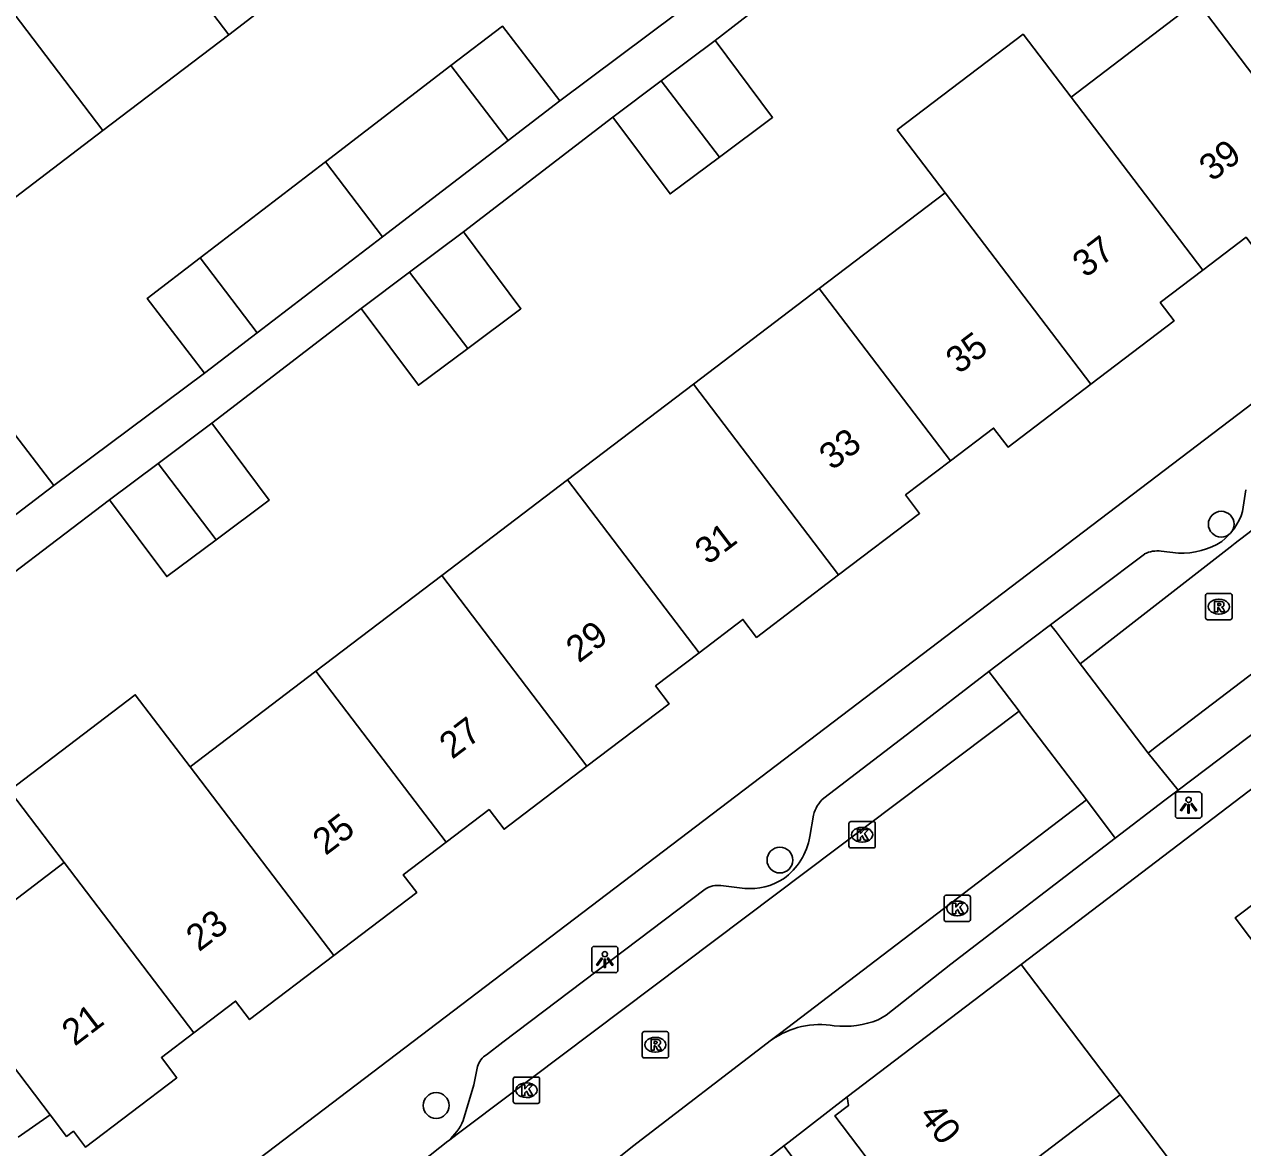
# Model space of a CAD drawing. Extents: x 160037 to 160839, y 385326 to 386441.
# Drawn here: x 160402.85 to 160449.09, y 385706.97 to 385749.61 of the extents above; entities that cross this region are included whole.
import ezdxf

# ---------------------------------------------------------------- set-up
doc = ezdxf.new("R2010")
doc.units = 0
for name, color, linetype in [('IMGEO_Boom', 7, 'Continuous'), ('IMGEO_Erf', 7, 'Continuous'), ('IMGEO_Kolk', 7, 'Continuous'), ('IMGEO_Lichtpunt', 7, 'Continuous'), ('IMGEO_Muur', 7, 'Continuous'), ('IMGEO_Pand', 7, 'Continuous'), ('IMGEO_Pand_nummerreeks', 7, 'Continuous'), ('IMGEO_Rijbaan_lokaal_open', 7, 'Continuous'), ('IMGEO_Rioolput', 7, 'Continuous'), ('IMGEO_Voetpad_open', 7, 'Continuous')]:
    doc.layers.add(name, color=color, linetype=linetype)

msp = doc.modelspace()

# ---------------------------------------------------------------- linework, layer by layer
at = {"layer": 'IMGEO_Boom'}
for centre in [(160448.279, 385730.633), (160431.529, 385717.884), (160418.482, 385708.569)]:
    msp.add_circle(centre, 0.489, dxfattribs=at)
at = {"layer": 'IMGEO_Erf'}
msp.add_lwpolyline([(160403.833, 385708.209), (160402.624, 385707.372)], dxfattribs=at)
at = {"layer": 'IMGEO_Kolk'}
for p, q in [((160434.148, 385718.419), (160434.148, 385719.271)), ((160434.223, 385719.345), (160435.075, 385719.345)), ((160435.149, 385719.271), (160435.149, 385718.419)), ((160434.636, 385719.125), (160434.661, 385719.125)), ((160435.075, 385718.345), (160434.223, 385718.345)), ((160434.659, 385718.565), (160434.634, 385718.565)), ((160437.761, 385715.624), (160437.761, 385716.476)), ((160437.836, 385716.55), (160438.688, 385716.55)), ((160438.762, 385716.476), (160438.762, 385715.624)), ((160438.249, 385716.33), (160438.274, 385716.33)), ((160438.688, 385715.55), (160437.836, 385715.55)), ((160438.272, 385715.77), (160438.247, 385715.77)), ((160421.409, 385708.722), (160421.409, 385709.574)), ((160421.484, 385709.648), (160422.336, 385709.648)), ((160422.41, 385709.574), (160422.41, 385708.722)), ((160421.897, 385709.428), (160421.922, 385709.428)), ((160422.336, 385708.648), (160421.484, 385708.648)), ((160421.92, 385708.868), (160421.895, 385708.868))]:
    msp.add_line(p, q, dxfattribs=at)
for points in [[(160434.148, 385718.419), (160434.148, 385719.271)], [(160434.223, 385719.345), (160435.075, 385719.345)], [(160435.149, 385719.271), (160435.149, 385718.419)], [(160434.469, 385719.045), (160434.592, 385719.045), (160434.592, 385718.894), (160434.722, 385719.045), (160434.886, 385719.045), (160434.74, 385718.894), (160434.893, 385718.645), (160434.741, 385718.645), (160434.656, 385718.809), (160434.592, 385718.742), (160434.592, 385718.645), (160434.469, 385718.645), (160434.469, 385719.045)], [(160435.075, 385718.345), (160434.223, 385718.345)], [(160437.761, 385715.624), (160437.761, 385716.476)], [(160437.836, 385716.55), (160438.688, 385716.55)], [(160438.762, 385716.476), (160438.762, 385715.624)], [(160438.082, 385716.25), (160438.205, 385716.25), (160438.205, 385716.099), (160438.335, 385716.25), (160438.499, 385716.25), (160438.353, 385716.099), (160438.506, 385715.85), (160438.354, 385715.85), (160438.269, 385716.014), (160438.205, 385715.947), (160438.205, 385715.85), (160438.082, 385715.85), (160438.082, 385716.25)], [(160438.688, 385715.55), (160437.836, 385715.55)], [(160421.409, 385708.722), (160421.409, 385709.574)], [(160421.484, 385709.648), (160422.336, 385709.648)], [(160422.41, 385709.574), (160422.41, 385708.722)], [(160421.73, 385709.348), (160421.853, 385709.348), (160421.853, 385709.197), (160421.983, 385709.348), (160422.147, 385709.348), (160422.001, 385709.197), (160422.154, 385708.948), (160422.002, 385708.948), (160421.917, 385709.112), (160421.853, 385709.045), (160421.853, 385708.948), (160421.73, 385708.948), (160421.73, 385709.348)], [(160422.336, 385708.648), (160421.484, 385708.648)]]:
    msp.add_lwpolyline(points, dxfattribs=at)
for centre, start, end in [((160434.225, 385719.269), 91.552, 178.448), ((160434.225, 385719.269), 91.552, 178.448), ((160435.073, 385719.269), 1.552, 88.448), ((160435.073, 385719.269), 1.552, 88.448), ((160434.225, 385718.421), 181.552, 268.448), ((160434.225, 385718.421), 181.552, 268.448), ((160435.073, 385718.421), 271.552, 358.448), ((160435.073, 385718.421), 271.552, 358.448), ((160437.838, 385716.474), 91.552, 178.448), ((160437.838, 385716.474), 91.552, 178.448), ((160438.686, 385716.474), 1.552, 88.448), ((160438.686, 385716.474), 1.552, 88.448), ((160437.838, 385715.626), 181.552, 268.448), ((160437.838, 385715.626), 181.552, 268.448), ((160438.686, 385715.626), 271.552, 358.448), ((160438.686, 385715.626), 271.552, 358.448), ((160421.486, 385709.572), 91.552, 178.448), ((160421.486, 385709.572), 91.552, 178.448), ((160422.334, 385709.572), 1.552, 88.448), ((160422.334, 385709.572), 1.552, 88.448), ((160421.486, 385708.724), 181.552, 268.448), ((160421.486, 385708.724), 181.552, 268.448), ((160422.334, 385708.724), 271.552, 358.448), ((160422.334, 385708.724), 271.552, 358.448)]:
    msp.add_arc(centre, 0.0765, start, end, dxfattribs=at)
for centre, major_axis, ratio, start_param, end_param in [((160434.635, 385718.845), (-0.387, 0.002), 0.722429, 4.712389, 7.853982), ((160434.66, 385718.845), (-0.39, 0.002), 0.717154, 1.570796, 4.712389), ((160438.248, 385716.05), (-0.387, 0.002), 0.722429, 4.712389, 7.853982), ((160438.273, 385716.05), (-0.39, 0.002), 0.717154, 1.570796, 4.712389), ((160421.896, 385709.148), (-0.387, 0.002), 0.722429, 4.712389, 7.853982), ((160421.921, 385709.148), (-0.39, 0.002), 0.717154, 1.570796, 4.712389)]:
    msp.add_ellipse(centre, major_axis=major_axis, ratio=ratio, start_param=start_param, end_param=end_param, dxfattribs=at)
at = {"layer": 'IMGEO_Lichtpunt'}
for p, q in [((160446.541, 385720.374), (160446.541, 385719.567)), ((160446.541, 385720.374), (160446.541, 385719.567)), ((160447.443, 385720.469), (160446.635, 385720.469)), ((160447.443, 385720.469), (160446.635, 385720.469)), ((160447.537, 385719.567), (160447.537, 385720.374)), ((160447.537, 385719.567), (160447.537, 385720.374)), ((160446.635, 385719.473), (160447.443, 385719.473)), ((160446.635, 385719.473), (160447.443, 385719.473)), ((160425.288, 385714.607), (160424.48, 385714.607)), ((160425.288, 385714.607), (160424.48, 385714.607)), ((160424.386, 385714.512), (160424.386, 385713.705)), ((160424.386, 385714.512), (160424.386, 385713.705)), ((160425.382, 385713.705), (160425.382, 385714.512)), ((160425.382, 385713.705), (160425.382, 385714.512)), ((160424.48, 385713.611), (160425.288, 385713.611)), ((160424.48, 385713.611), (160425.288, 385713.611))]:
    msp.add_line(p, q, dxfattribs=at)
for points in [[(160446.915, 385720.038), (160446.954, 385720.01), (160446.766, 385719.748), (160446.728, 385719.775), (160446.915, 385720.038)], [(160447.017, 385719.99), (160447.064, 385719.99), (160447.064, 385719.668), (160447.017, 385719.668), (160447.017, 385719.99)], [(160447.127, 385720.01), (160447.165, 385720.037), (160447.352, 385719.775), (160447.313, 385719.747), (160447.127, 385720.01)], [(160424.76, 385714.176), (160424.799, 385714.148), (160424.611, 385713.886), (160424.573, 385713.913), (160424.76, 385714.176)], [(160424.972, 385714.148), (160425.01, 385714.175), (160425.197, 385713.913), (160425.158, 385713.885), (160424.972, 385714.148)], [(160424.862, 385714.128), (160424.909, 385714.128), (160424.909, 385713.806), (160424.862, 385713.806), (160424.862, 385714.128)]]:
    msp.add_lwpolyline(points, dxfattribs=at)
for centre in [(160447.04, 385720.172), (160424.885, 385714.31)]:
    msp.add_circle(centre, 0.0994, dxfattribs=at)
for centre, start, end in [((160446.635, 385720.374), 90, 180), ((160446.635, 385720.374), 90, 180), ((160447.443, 385720.374), 0, 90), ((160447.443, 385720.374), 0, 90), ((160446.635, 385719.567), 180, 270), ((160446.635, 385719.567), 180, 270), ((160447.443, 385719.567), 270, 0), ((160447.443, 385719.567), 270, 360), ((160424.48, 385714.512), 90, 180), ((160424.48, 385714.512), 90, 180), ((160425.288, 385714.512), 0, 90), ((160425.288, 385714.512), 0, 90), ((160424.48, 385713.705), 180, 270), ((160424.48, 385713.705), 180, 270), ((160425.288, 385713.705), 270, 0), ((160425.288, 385713.705), 270, 360)]:
    msp.add_arc(centre, 0.0946, start, end, dxfattribs=at)
at = {"layer": 'IMGEO_Muur'}
msp.add_lwpolyline([(160449.644, 385720.741), (160449.342, 385720.511), (160440.682, 385713.917)], dxfattribs=at)
at = {"layer": 'IMGEO_Pand'}
for points in [[(160410.611, 385749.212), (160410.011, 385750), (160405.606, 385755.787)], [(160400.314, 385752.834), (160402.472, 385750), (160405.838, 385745.578)], [(160410.611, 385749.212), (160411.646, 385750), (160415.385, 385752.847)], [(160447.353, 385750.475), (160446.728, 385750), (160442.577, 385746.843)], [(160447.353, 385750.475), (160447.714, 385750), (160452.864, 385743.228)], [(160423.172, 385746.702), (160420.997, 385749.539), (160419.044, 385748.041)], [(160405.838, 385745.578), (160410.611, 385749.212)], [(160427.028, 385747.465), (160429.076, 385748.994)], [(160429.232, 385744.567), (160431.254, 385746.077), (160429.076, 385748.994)], [(160442.577, 385746.843), (160440.761, 385749.231), (160435.985, 385745.6), (160437.801, 385743.212)], [(160419.044, 385748.041), (160414.282, 385744.39)], [(160421.21, 385745.197), (160419.044, 385748.041)], [(160425.186, 385746.089), (160427.028, 385747.465)], [(160429.232, 385744.567), (160427.028, 385747.465)], [(160423.172, 385746.702), (160421.21, 385745.197)], [(160447.575, 385740.27), (160442.577, 385746.843)], [(160425.186, 385746.089), (160427.364, 385743.172), (160429.232, 385744.567)], [(160401.064, 385741.943), (160405.838, 385745.578)], [(160416.447, 385741.545), (160421.21, 385745.197)], [(160414.282, 385744.39), (160409.521, 385740.739)], [(160414.282, 385744.39), (160416.447, 385741.545)], [(160437.801, 385743.212), (160433.025, 385739.58)], [(160437.801, 385743.212), (160443.324, 385735.948)], [(160452.864, 385743.228), (160449.736, 385740.849), (160449.223, 385741.523), (160447.575, 385740.27)], [(160411.687, 385737.894), (160416.447, 385741.545)], [(160419.524, 385741.73), (160417.477, 385740.202)], [(160419.681, 385737.304), (160421.702, 385738.813), (160419.524, 385741.73)], [(160409.521, 385740.739), (160407.515, 385739.201), (160409.69, 385736.363)], [(160411.687, 385737.894), (160409.521, 385740.739)], [(160417.477, 385740.202), (160415.634, 385738.825)], [(160419.681, 385737.304), (160417.477, 385740.202)], [(160447.575, 385740.27), (160445.963, 385739.044), (160446.488, 385738.354), (160443.324, 385735.948)], [(160433.025, 385739.58), (160428.25, 385735.948)], [(160433.025, 385739.58), (160438.001, 385733.037)], [(160415.634, 385738.825), (160417.812, 385735.908), (160419.681, 385737.304)], [(160409.69, 385736.363), (160411.687, 385737.894)], [(160428.25, 385735.948), (160423.473, 385732.316)], [(160428.25, 385735.948), (160433.756, 385728.707)], [(160443.324, 385735.948), (160440.188, 385733.563), (160439.64, 385734.284), (160438.001, 385733.037)], [(160403.968, 385732.099), (160401.824, 385734.899), (160399.967, 385733.477)], [(160407.926, 385732.937), (160409.973, 385734.466)], [(160410.129, 385730.039), (160412.151, 385731.549), (160409.973, 385734.466)], [(160407.926, 385732.937), (160406.083, 385731.561)], [(160410.129, 385730.039), (160410.093, 385730.086), (160407.926, 385732.937)], [(160438.001, 385733.037), (160436.3, 385731.744), (160436.831, 385731.045), (160433.756, 385728.707)], [(160423.473, 385732.316), (160418.697, 385728.684)], [(160428.463, 385725.753), (160423.473, 385732.316)], [(160402.103, 385730.671), (160403.968, 385732.099)], [(160406.083, 385731.561), (160408.261, 385728.644), (160410.129, 385730.039)], [(160418.697, 385728.684), (160413.922, 385725.052)], [(160418.697, 385728.684), (160424.201, 385721.445)], [(160433.756, 385728.707), (160430.641, 385726.339), (160430.126, 385727.017), (160428.463, 385725.753)], [(160428.463, 385725.753), (160426.81, 385724.496), (160427.324, 385723.82), (160424.201, 385721.445)], [(160413.922, 385725.052), (160409.146, 385721.42)], [(160413.922, 385725.052), (160418.858, 385718.561)], [(160409.146, 385721.42), (160407.063, 385724.16), (160402.287, 385720.529), (160404.37, 385717.789)], [(160414.593, 385714.256), (160409.146, 385721.42)], [(160424.201, 385721.445), (160421.059, 385719.056), (160420.491, 385719.803), (160418.858, 385718.561)], [(160418.858, 385718.561), (160417.236, 385717.328), (160417.747, 385716.655), (160414.593, 385714.256)], [(160403.833, 385708.209), (160399.414, 385714.02), (160404.37, 385717.789)], [(160404.37, 385717.789), (160409.284, 385711.326)], [(160450.438, 385713.531), (160448.812, 385715.696), (160451.482, 385717.701)], [(160414.593, 385714.256), (160411.402, 385711.83), (160410.869, 385712.532), (160409.284, 385711.326)], [(160440.682, 385713.917), (160434.085, 385708.897)], [(160440.682, 385713.917), (160443.71, 385709.938), (160444.446, 385708.971)], [(160409.284, 385711.326), (160408.053, 385710.39), (160408.64, 385709.619), (160405.176, 385706.985), (160404.715, 385707.591), (160404.454, 385707.393), (160403.833, 385708.209)], [(160437.999, 385704.064), (160436.754, 385705.701), (160435.955, 385705.093), (160433.61, 385708.175), (160434.127, 385708.568), (160434.085, 385708.897)], [(160444.446, 385708.971), (160437.999, 385704.064)], [(160444.446, 385708.971), (160448.079, 385704.196)]]:
    msp.add_lwpolyline(points, dxfattribs=at)
at = {"layer": 'IMGEO_Rijbaan_lokaal_open'}
for points in [[(160442.926, 385725.336), (160448.737, 385729.856), (160448.762, 385729.875), (160460.742, 385739.019), (160461.382, 385739.566)], [(160445.5, 385721.947), (160445.769, 385722.152), (160461, 385733.756), (160461.267, 385733.959)], [(160441.802, 385726.815), (160440.461, 385725.805), (160439.461, 385725.037)], [(160441.802, 385726.815), (160442.008, 385726.544), (160442.926, 385725.336)], [(160445.5, 385721.947), (160443.018, 385725.214), (160442.926, 385725.336)], [(160439.461, 385725.037), (160439.669, 385724.763), (160440.604, 385723.533)], [(160418.95, 385707.231), (160419.336, 385707.522), (160419.79, 385707.863), (160440.604, 385723.533)], [(160440.604, 385723.533), (160440.679, 385723.434), (160443.162, 385720.166)], [(160446.64, 385720.537), (160445.5, 385721.947)], [(160443.162, 385720.166), (160431.562, 385711.329), (160431.215, 385711.065)], [(160444.25, 385718.71), (160443.162, 385720.166)], [(160444.25, 385718.71), (160446.14, 385720.159), (160446.64, 385720.537)], [(160423.388, 385704.97), (160425.94, 385707.013), (160431.215, 385711.065)], [(160417.011, 385705.558), (160417.949, 385706.438), (160418.929, 385707.215), (160418.95, 385707.231)]]:
    msp.add_lwpolyline(points, dxfattribs=at)
at = {"layer": 'IMGEO_Rioolput'}
for p, q in [((160447.687, 385727.078), (160447.687, 385727.93)), ((160447.762, 385728.004), (160448.614, 385728.004)), ((160448.175, 385727.784), (160448.2, 385727.784)), ((160448.688, 385727.93), (160448.688, 385727.078)), ((160448.198, 385727.224), (160448.173, 385727.224)), ((160448.614, 385727.004), (160447.762, 385727.004)), ((160426.376, 385711.374), (160427.228, 385711.374)), ((160426.301, 385710.448), (160426.301, 385711.3)), ((160426.789, 385711.154), (160426.814, 385711.154)), ((160427.302, 385711.3), (160427.302, 385710.448)), ((160426.812, 385710.594), (160426.787, 385710.594)), ((160427.228, 385710.374), (160426.376, 385710.374))]:
    msp.add_line(p, q, dxfattribs=at)
for points in [[(160447.687, 385727.078), (160447.687, 385727.93)], [(160447.762, 385728.004), (160448.614, 385728.004)], [(160448.276, 385727.702), (160448.024, 385727.704), (160448.024, 385727.304)], [(160448.202, 385727.623), (160448.148, 385727.623), (160448.148, 385727.542)], [(160448.688, 385727.93), (160448.688, 385727.078)], [(160448.024, 385727.304), (160448.148, 385727.304), (160448.148, 385727.466), (160448.159, 385727.466)], [(160448.148, 385727.542), (160448.2, 385727.542)], [(160448.206, 385727.437), (160448.277, 385727.304), (160448.417, 385727.304), (160448.352, 385727.43)], [(160448.614, 385727.004), (160447.762, 385727.004)], [(160426.376, 385711.374), (160427.228, 385711.374)], [(160426.301, 385710.448), (160426.301, 385711.3)], [(160426.89, 385711.072), (160426.638, 385711.074), (160426.638, 385710.674)], [(160426.816, 385710.993), (160426.762, 385710.993), (160426.762, 385710.912)], [(160426.762, 385710.912), (160426.814, 385710.912)], [(160427.302, 385711.3), (160427.302, 385710.448)], [(160426.638, 385710.674), (160426.762, 385710.674), (160426.762, 385710.836), (160426.773, 385710.836)], [(160426.82, 385710.807), (160426.891, 385710.674), (160427.031, 385710.674), (160426.966, 385710.8)], [(160427.228, 385710.374), (160426.376, 385710.374)]]:
    msp.add_lwpolyline(points, dxfattribs=at)
for centre, radius, start, end in [((160447.764, 385727.928), 0.0765, 91.552, 178.448), ((160447.764, 385727.928), 0.0765, 91.552, 178.448), ((160448.208, 385727.527), 0.0964, 77.0061, 93.1865), ((160448.222, 385727.584), 0.0378, 276.6634, 79.6772), ((160448.275, 385727.592), 0.109, 350.3612, 89.416), ((160448.273, 385727.592), 0.112, 277.5842, 350.9817), ((160448.612, 385727.928), 0.0765, 1.552, 88.448), ((160448.612, 385727.928), 0.0765, 1.552, 88.448), ((160448.158, 385727.413), 0.0533, 26.0293, 88.6989), ((160448.184, 385727.731), 0.19, 274.7715, 282.9687), ((160448.257, 385727.377), 0.108, 29.5134, 73.7905), ((160447.764, 385727.08), 0.0765, 181.552, 268.448), ((160447.764, 385727.08), 0.0765, 181.552, 268.448), ((160448.612, 385727.08), 0.0765, 271.552, 358.448), ((160448.612, 385727.08), 0.0765, 271.552, 358.448), ((160426.378, 385711.298), 0.0765, 91.552, 178.448), ((160426.378, 385711.298), 0.0765, 91.552, 178.448), ((160427.226, 385711.298), 0.0765, 1.552, 88.448), ((160427.226, 385711.298), 0.0765, 1.552, 88.448), ((160426.798, 385711.101), 0.19, 274.7715, 282.9687), ((160426.822, 385710.897), 0.0964, 77.0061, 93.1865), ((160426.836, 385710.954), 0.0378, 276.6634, 79.6772), ((160426.889, 385710.962), 0.109, 350.3612, 89.416), ((160426.887, 385710.962), 0.112, 277.5842, 350.9817), ((160426.378, 385710.45), 0.0765, 181.552, 268.448), ((160426.378, 385710.45), 0.0765, 181.552, 268.448), ((160426.772, 385710.783), 0.0533, 26.0293, 88.6989), ((160426.871, 385710.747), 0.108, 29.5134, 73.7905), ((160427.226, 385710.45), 0.0765, 271.552, 358.448), ((160427.226, 385710.45), 0.0765, 271.552, 358.448)]:
    msp.add_arc(centre, radius, start, end, dxfattribs=at)
for centre, major_axis, ratio, start_param, end_param in [((160448.174, 385727.504), (-0.387, 0.002), 0.722429, 4.712389, 7.853982), ((160448.199, 385727.504), (-0.39, 0.002), 0.717154, 1.570796, 4.712389), ((160426.788, 385710.874), (-0.387, 0.002), 0.722429, 4.712389, 7.853982), ((160426.813, 385710.874), (-0.39, 0.002), 0.717154, 1.570796, 4.712389)]:
    msp.add_ellipse(centre, major_axis=major_axis, ratio=ratio, start_param=start_param, end_param=end_param, dxfattribs=at)
at = {"layer": 'IMGEO_Voetpad_open'}
for points in [[(160429.076, 385748.994), (160431.915, 385751.209)], [(160428.786, 385750.901), (160423.172, 385746.702)], [(160419.524, 385741.73), (160425.186, 385746.089)], [(160440.882, 385659.407), (160407.478, 385703.294), (160463, 385745.517)], [(160409.973, 385734.466), (160415.634, 385738.825)], [(160409.69, 385736.363), (160403.968, 385732.099)], [(160449.213, 385731.941), (160449.091, 385731.113)], [(160400.184, 385727.073), (160406.083, 385731.561)], [(160446.64, 385720.537), (160454.889, 385726.781), (160459.579, 385730.435)], [(160445.367, 385729.502), (160441.802, 385726.815)], [(160446.656, 385729.533), (160445.999, 385729.607)], [(160433.195, 385720.23), (160436.537, 385722.794), (160439.461, 385725.037)], [(160449.342, 385720.511), (160440.682, 385713.917)], [(160432.66, 385718.775), (160432.802, 385719.594)], [(160435.257, 385711.822), (160435.568, 385712.002), (160438.016, 385713.932), (160444.25, 385718.71)], [(160429.287, 385716.918), (160430.195, 385716.811)], [(160420.395, 385710.497), (160421.016, 385710.975), (160428.692, 385716.783)], [(160419.511, 385707.995), (160419.909, 385709.347), (160420.057, 385710.046)], [(160434.085, 385708.897), (160431.881, 385707.185), (160431.683, 385707.035)], [(160431.683, 385707.035), (160430.84, 385706.394)], [(160431.683, 385707.035), (160432.872, 385705.471)]]:
    msp.add_lwpolyline(points, dxfattribs=at)
for centre, radius, start, end in [((160446.769, 385731.89), 2.449, 308.7045, 341.5016), ((160446.768, 385732.371), 2.841, 267.7314, 302.6255), ((160445.847, 385728.569), 1.05, 81.6627, 117.2032), ((160433.99, 385719.299), 1.224, 130.5054, 166.0687), ((160430.239, 385719.174), 2.453, 305.5571, 350.6453), ((160429.18, 385716.009), 0.915, 83.3069, 122.26), ((160430.399, 385719.124), 2.322, 264.9525, 303.065), ((160433.067, 385708.374), 3.267, 80.7605, 124.5268), ((160433.988, 385714.954), 3.379, 263.2547, 292.0607), ((160420.784, 385709.853), 0.752, 121.1509, 165.15), ((160417.422, 385708.941), 2.293, 311.7802, 335.6406)]:
    msp.add_arc(centre, radius, start, end, dxfattribs=at)

# ---------------------------------------------------------------- texts
at = {"layer": 'IMGEO_Pand_nummerreeks'}
for s, rotation, p in [('39', 37.2448, (160447.929, 385743.612)), ('37', 37.2423, (160443.123, 385739.959)), ('35', 37.2423, (160438.317, 385736.305)), ('33', 37.2448, (160433.511, 385732.65)), ('31', 37.2448, (160428.795, 385729.064)), ('29', 37.2448, (160423.899, 385725.342)), ('27', 37.2448, (160419.092, 385721.688)), ('25', 37.2448, (160414.286, 385718.034)), ('23', 37.2423, (160409.48, 385714.381)), ('21', 37.2423, (160404.764, 385710.795)), ('40', 307.3382, (160436.774, 385708.184))]:
    msp.add_text(s, height=1, rotation=rotation, dxfattribs=at).set_placement(p)

doc.saveas('drawing.dxf')
